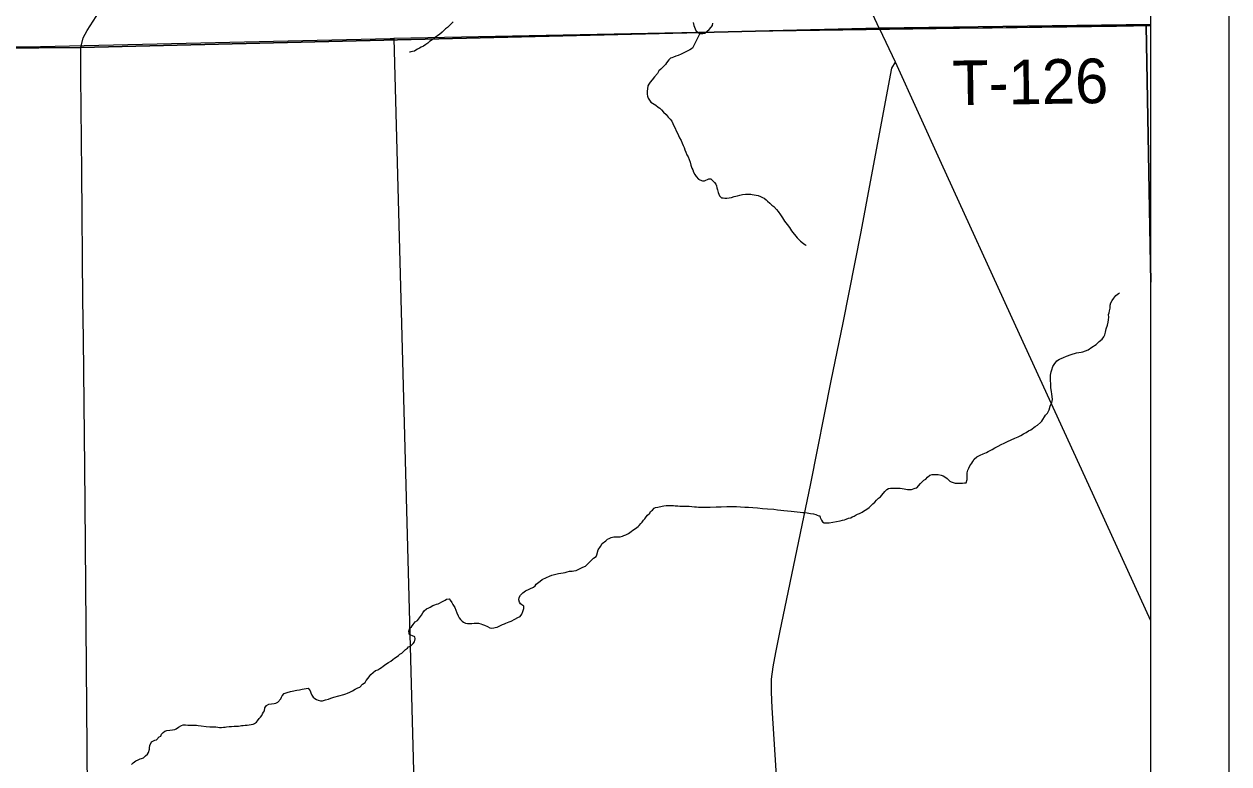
# Model space of a CAD drawing. Extents: x 10.6 to 44.6, y -2.6 to 23.4.
# Drawn here: x 18.57 to 20.103, y 20.016 to 20.958 of the extents above; entities that cross this region are included whole.
import ezdxf

# ---------------------------------------------------------------- set-up
doc = ezdxf.new("R2010")
doc.units = 0
for name, color, linetype in [('GM_X_County', 7, 'Continuous'), ('GM_X_County_Road', 7, 'Continuous'), ('GM_X_Minor_Lake', 7, 'Continuous'), ('GM_X_Minor_River', 7, 'Continuous'), ('GM_X_Section', 7, 'Continuous'), ('GM_X_State_Route', 7, 'Continuous'), ('GM_X_Township', 7, 'Continuous'), ('GM_X_Township_Road', 7, 'Continuous'), ('GM_X_Township_Road_Text', 7, 'Continuous'), ('SH_Data', 7, 'Continuous')]:
    doc.layers.add(name, color=color, linetype=linetype)

msp = doc.modelspace()

# ---------------------------------------------------------------- linework, layer by layer
at = {"layer": 'GM_X_County'}
msp.add_lwpolyline([(20.0033, 15.5302), (20.0033, 22.3267), (13.2033, 22.3267), (13.2033, 15.5267), (19.8413, 15.5267)], dxfattribs=at)
at = {"layer": 'GM_X_County_Road'}
for points in [[(18.6535, 19.6817), (18.6533, 19.7284), (18.6525, 19.7533), (18.6516, 19.8149), (18.6497, 20.0361), (18.6472, 20.3469), (18.6468, 20.3934), (18.645, 20.5569), (18.6444, 20.6072), (18.643, 20.7692), (18.6417, 20.8913), (18.6416, 20.9277), (18.6445, 20.9403), (18.6498, 20.9497), (18.669, 20.9792), (18.7118, 21.0385)], [(19.5512, 19.5913), (19.5484, 19.6433), (19.5465, 19.6819), (19.5455, 19.7043), (19.5377, 19.8318), (19.5279, 19.9874), (19.5216, 20.0873), (19.5206, 20.1073), (19.5206, 20.1237), (19.5228, 20.1393), (19.526, 20.1578), (19.5311, 20.1832), (19.5709, 20.373), (19.5968, 20.5034), (19.6117, 20.5772), (19.6346, 20.6932), (19.6468, 20.7569), (19.6737, 20.9017), (19.6783, 20.9093)]]:
    msp.add_lwpolyline(points, dxfattribs=at)
at = {"layer": 'GM_X_Minor_Lake'}
msp.add_lwpolyline([(19.4209, 20.9599), (19.4217, 20.9561), (19.4228, 20.9538), (19.4244, 20.9496), (19.4274, 20.947), (19.4293, 20.9459), (19.4312, 20.9459), (19.4335, 20.9459), (19.4358, 20.9463), (19.4388, 20.9486), (19.4414, 20.9509), (19.4441, 20.9536), (19.4456, 20.9559), (19.4459, 20.9589)], dxfattribs=at)
at = {"layer": 'GM_X_Minor_River'}
for points in [[(19.1157, 20.9607), (19.1082, 20.9534), (19.1059, 20.9515), (19.1041, 20.9499), (19.1014, 20.9473), (19.098, 20.9446), (19.0961, 20.943), (19.0939, 20.9415), (19.092, 20.94), (19.0901, 20.9384), (19.0875, 20.9369), (19.0856, 20.9354), (19.0833, 20.9334), (19.0807, 20.9319), (19.078, 20.9296), (19.075, 20.9281), (19.0727, 20.9269), (19.0701, 20.9258), (19.0682, 20.9246), (19.0663, 20.9234), (19.064, 20.9227), (19.0618, 20.9223), (19.0606, 20.9219), (19.0602, 20.9219)], [(19.4293, 20.9459), (19.42, 20.9272), (19.4166, 20.9249), (19.4124, 20.9229), (19.409, 20.921), (19.4056, 20.9195), (19.4019, 20.9179), (19.3988, 20.9168), (19.3958, 20.9156), (19.3939, 20.9148), (19.392, 20.9141), (19.3901, 20.9121), (19.3871, 20.9083), (19.3856, 20.9064), (19.3826, 20.903), (19.38, 20.9003), (19.3773, 20.898), (19.3755, 20.8946), (19.3717, 20.8907), (19.3687, 20.8869), (19.3661, 20.8838), (19.3646, 20.8812), (19.3634, 20.8789), (19.3624, 20.8717), (19.3624, 20.8686), (19.3628, 20.866), (19.3639, 20.8633), (19.3655, 20.8607), (19.367, 20.8584), (19.3693, 20.8569), (19.3712, 20.8558), (19.3735, 20.8543), (19.3765, 20.852), (19.3785, 20.8505), (19.3807, 20.8486), (19.3834, 20.8456), (19.3865, 20.8426), (19.3892, 20.8392), (19.3918, 20.8365), (19.3938, 20.8339), (19.3953, 20.8313), (19.3965, 20.8282), (19.398, 20.8252), (19.3995, 20.8218), (19.4011, 20.8188), (19.4023, 20.8157), (19.4038, 20.8127), (19.4057, 20.8093), (19.4069, 20.8063), (19.4084, 20.8032), (19.4096, 20.8006), (19.4104, 20.7975), (19.4115, 20.7945), (19.4131, 20.7911), (19.4146, 20.7885), (19.4158, 20.7854), (19.4173, 20.782), (19.4181, 20.7782), (19.4193, 20.7744), (19.4204, 20.7722), (19.4216, 20.7691), (19.4231, 20.7661), (19.425, 20.7635), (19.4277, 20.7604), (19.4296, 20.7593), (19.4327, 20.7582), (19.4353, 20.7582), (19.441, 20.7605), (19.4433, 20.7609), (19.446, 20.7583), (19.4483, 20.756), (19.4498, 20.7538), (19.4509, 20.7519), (19.4513, 20.7492), (19.4521, 20.7466), (19.4529, 20.7431), (19.4537, 20.7413), (19.4545, 20.739), (19.4571, 20.7367), (19.459, 20.7363), (19.4613, 20.736), (19.464, 20.736), (19.467, 20.7364), (19.4696, 20.7368), (19.4731, 20.738), (19.4753, 20.7387), (19.4776, 20.7391), (19.4803, 20.7399), (19.4837, 20.7407), (19.4878, 20.7411), (19.4916, 20.7411), (19.4943, 20.7412), (19.4962, 20.7408), (19.4985, 20.7404), (19.5011, 20.7401), (19.5038, 20.7393)], [(19.5038, 20.7393), (19.5068, 20.7382), (19.5091, 20.7371), (19.5114, 20.736), (19.5137, 20.7341), (19.5156, 20.7322), (19.5187, 20.7299), (19.5213, 20.7273), (19.5236, 20.7254), (19.5271, 20.7216), (19.529, 20.719), (19.5321, 20.7148), (19.5347, 20.7111), (19.5374, 20.7069), (19.5405, 20.7024), (19.5436, 20.6986), (19.5463, 20.6944), (19.5532, 20.6857), (19.5551, 20.6839), (19.5574, 20.6812), (19.5593, 20.6801), (19.5619, 20.6778), (19.5639, 20.6767), (19.565, 20.676)], [(19.7521, 20.3741), (19.7544, 20.3734), (19.7639, 20.3731), (19.7665, 20.3735), (19.7684, 20.3738), (19.7695, 20.378), (19.7695, 20.3822), (19.7695, 20.3845), (19.7695, 20.3864), (19.7706, 20.3898), (19.7717, 20.3925), (19.7732, 20.3952), (19.7755, 20.3986), (19.777, 20.4009), (19.7788, 20.4039), (19.7822, 20.4066), (19.7864, 20.4089), (19.7902, 20.4105), (19.7924, 20.4113), (19.7943, 20.4124), (19.7966, 20.4136), (19.7989, 20.4147), (19.8015, 20.4163), (19.8049, 20.4182), (19.8091, 20.4205), (19.8129, 20.4224), (19.817, 20.4244), (19.8212, 20.4263), (19.8257, 20.4286), (19.8303, 20.4305), (19.8348, 20.4321), (19.8382, 20.434), (19.8416, 20.4359), (19.845, 20.4379), (19.8476, 20.4398), (19.8507, 20.4413), (19.8563, 20.4455), (19.8594, 20.4471), (19.8631, 20.4505), (19.8646, 20.4524), (19.8695, 20.4597), (19.8718, 20.4624), (19.874, 20.4666), (19.8755, 20.4715), (19.8773, 20.4761), (19.8785, 20.4799), (19.878, 20.4837), (19.8773, 20.4867), (19.8769, 20.4898), (19.8765, 20.492), (19.8761, 20.4951), (19.876, 20.4993), (19.8756, 20.5042), (19.8756, 20.5084), (19.8759, 20.5107), (19.8763, 20.5129), (19.8767, 20.5149), (19.8774, 20.5175), (19.8789, 20.5217), (19.8804, 20.5244), (19.8838, 20.529), (19.8872, 20.5313), (19.8894, 20.532), (19.8925, 20.5332), (19.8963, 20.5348), (19.9019, 20.5371), (19.9087, 20.539), (19.9148, 20.5402), (19.9171, 20.5406), (19.9235, 20.5429), (19.9284, 20.5464), (19.9337, 20.5498), (19.9379, 20.5537), (19.9416, 20.5564), (19.9435, 20.5594), (19.945, 20.5621), (19.9457, 20.5655), (19.9468, 20.5697), (19.9483, 20.5743), (19.9491, 20.5781), (19.9494, 20.5811), (19.9498, 20.5845), (19.9497, 20.588), (19.9505, 20.5902), (19.9508, 20.5925), (19.9516, 20.596), (19.9519, 20.5998), (19.9527, 20.6028), (19.9542, 20.6058), (19.9564, 20.6089), (19.959, 20.6123), (19.9621, 20.6146), (19.9636, 20.6154)], [(19.4096, 20.3439), (19.4127, 20.3439), (19.4161, 20.3439), (19.4195, 20.3436), (19.4226, 20.3432), (19.4252, 20.3432), (19.4279, 20.3429), (19.4305, 20.3429), (19.4336, 20.3429), (19.4377, 20.3426), (19.4427, 20.3426), (19.4503, 20.343), (19.4567, 20.3431), (19.4639, 20.3435), (19.4704, 20.3436), (19.4761, 20.3436), (19.4814, 20.3433), (19.4867, 20.3429), (19.4916, 20.3426), (19.4969, 20.3422), (19.503, 20.3419), (19.5091, 20.3412), (19.5156, 20.3408), (19.5235, 20.3401), (19.5285, 20.3394), (19.5326, 20.3391), (19.5364, 20.3383), (19.541, 20.338), (19.5456, 20.3376), (19.5497, 20.3373), (19.5535, 20.3366), (19.5573, 20.3362), (19.5604, 20.3358), (19.563, 20.3359), (19.5661, 20.3355), (19.5684, 20.3351), (19.5703, 20.3348), (19.5741, 20.3341), (19.5771, 20.3333), (19.579, 20.3326), (19.5809, 20.3318), (19.5824, 20.3315), (19.5828, 20.3296), (19.5844, 20.3261), (19.5855, 20.3239), (19.5878, 20.3228), (19.5901, 20.3228), (19.5939, 20.3228), (19.5988, 20.3236), (19.6033, 20.3244), (19.6079, 20.3252), (19.6109, 20.326), (19.6136, 20.3267), (19.6158, 20.3275), (19.6185, 20.3287), (19.6215, 20.3291), (19.6234, 20.3302), (19.6257, 20.3314), (19.6283, 20.3329), (19.6302, 20.3337), (19.6325, 20.3345), (19.6359, 20.3364), (19.6378, 20.3376), (19.6401, 20.3391), (19.6419, 20.3402), (19.645, 20.3422), (19.6468, 20.3441), (19.6495, 20.3468), (19.6521, 20.3491), (19.6544, 20.3517), (19.657, 20.354), (19.6593, 20.356), (19.6612, 20.3579), (19.6649, 20.3628), (19.6676, 20.3651), (19.6698, 20.3663), (19.6721, 20.3667), (19.6755, 20.3667), (19.6786, 20.3667), (19.6846, 20.3668), (19.6896, 20.3661), (19.6937, 20.3653), (19.6968, 20.365), (19.6987, 20.365), (19.7036, 20.3669), (19.7055, 20.3673), (19.7104, 20.373), (19.7145, 20.3769), (19.7172, 20.3784), (19.7191, 20.3807), (19.7224, 20.3834), (19.7251, 20.3842), (19.7285, 20.3842), (19.7327, 20.3842), (19.7365, 20.3835), (19.7392, 20.3824), (19.7414, 20.3813), (19.7441, 20.379), (19.7476, 20.376), (19.7495, 20.3749), (19.7521, 20.3741)], [(19.1672, 20.189), (19.1691, 20.1894), (19.1717, 20.1901), (19.174, 20.1913), (19.1759, 20.1921), (19.1785, 20.1932), (19.1808, 20.1944), (19.1827, 20.1952), (19.1846, 20.1959), (19.1868, 20.1967), (19.1895, 20.1975), (19.194, 20.2002), (19.1978, 20.2021), (19.2008, 20.2036), (19.2031, 20.2063), (19.2042, 20.2101), (19.2057, 20.2139), (19.2053, 20.2166), (19.203, 20.2185), (19.2011, 20.2196), (19.1999, 20.2219), (19.1992, 20.2249), (19.1995, 20.2276), (19.2014, 20.2306), (19.2044, 20.2337), (19.2078, 20.236), (19.2176, 20.241), (19.2199, 20.2425), (19.2214, 20.2445), (19.2244, 20.2471), (19.2263, 20.2483), (19.2289, 20.2506), (19.2342, 20.2533), (19.238, 20.2548), (19.241, 20.256), (19.2429, 20.2564), (19.2463, 20.2576), (19.2498, 20.2583), (19.2528, 20.2587), (19.2554, 20.2591), (19.2581, 20.2595), (19.2607, 20.2603), (19.2638, 20.2611), (19.2672, 20.2611), (19.2691, 20.2615), (19.2721, 20.2623), (19.2748, 20.2635), (19.2782, 20.265), (19.2808, 20.2662), (19.2838, 20.2677), (19.2865, 20.27), (19.2902, 20.2738), (19.294, 20.2777), (19.2974, 20.28), (19.2982, 20.2819), (19.3, 20.2883), (19.303, 20.2925), (19.3053, 20.2964), (19.3098, 20.2998), (19.312, 20.3021), (19.3139, 20.3029), (19.3166, 20.304), (19.32, 20.3048), (19.3223, 20.3048), (19.3249, 20.3049), (19.328, 20.3049), (19.331, 20.3057), (19.3329, 20.3068), (19.3355, 20.3076), (19.3386, 20.3091), (19.3404, 20.3103), (19.3423, 20.3118), (19.3442, 20.3134), (19.3465, 20.3145), (19.3495, 20.3168), (19.351, 20.318), (19.3521, 20.3195), (19.3544, 20.3218), (19.3559, 20.3237), (19.3578, 20.326), (19.3597, 20.3279), (19.3612, 20.3302), (19.363, 20.3325), (19.3657, 20.3352), (19.3668, 20.3371), (19.3691, 20.339), (19.3713, 20.3413), (19.3732, 20.3421), (19.3759, 20.3429), (19.3816, 20.344), (19.3838, 20.3444), (19.3865, 20.3448), (19.3888, 20.3449), (19.391, 20.3449), (19.3937, 20.3449), (19.396, 20.3449), (19.3979, 20.3445), (19.4017, 20.3446), (19.4039, 20.3442), (19.4062, 20.3442), (19.4096, 20.3439)], [(18.9309, 20.1124), (18.9336, 20.109), (18.9344, 20.1063), (18.9359, 20.1033), (18.9375, 20.101), (18.9394, 20.0991), (18.9417, 20.098), (18.9439, 20.0969), (18.9466, 20.0961), (18.9493, 20.0962), (18.9531, 20.0973), (18.9568, 20.0985), (18.9599, 20.0997), (18.9636, 20.1008), (18.9765, 20.1044), (18.9788, 20.1051), (18.9811, 20.1059), (18.9841, 20.1074), (18.9875, 20.109), (18.9909, 20.1109), (18.9943, 20.1128), (18.9966, 20.1136), (19.0003, 20.1174), (19.0034, 20.1194), (19.0049, 20.122), (19.0075, 20.1251), (19.0097, 20.1278), (19.0109, 20.1297), (19.0139, 20.1324), (19.0169, 20.135), (19.0199, 20.1358), (19.0222, 20.1374), (19.0245, 20.1385), (19.0267, 20.1404), (19.0297, 20.1427), (19.0331, 20.145), (19.0362, 20.1466), (19.0388, 20.1489), (19.0407, 20.1504), (19.043, 20.1516), (19.046, 20.1539), (19.0479, 20.1554), (19.0501, 20.1569), (19.0524, 20.1589), (19.055, 20.1615), (19.0573, 20.1631), (19.0588, 20.165), (19.0611, 20.1658), (19.0648, 20.1692), (19.0663, 20.1711), (19.0671, 20.1753), (19.0667, 20.1776), (19.064, 20.1791), (19.0617, 20.1798), (19.0598, 20.1802), (19.059, 20.1847), (19.0605, 20.1886), (19.0624, 20.1905), (19.0647, 20.1935), (19.0673, 20.1966), (19.0703, 20.1985), (19.0729, 20.202), (19.0752, 20.2054), (19.0771, 20.2084), (19.0786, 20.2107), (19.0816, 20.2134), (19.0846, 20.2146), (19.0865, 20.2153), (19.0899, 20.2177), (19.0922, 20.2184), (19.0944, 20.2192), (19.0963, 20.2196), (19.1028, 20.2231), (19.1054, 20.2242), (19.1073, 20.2254), (19.1103, 20.2262), (19.1119, 20.2243), (19.1138, 20.2212), (19.1153, 20.2186), (19.1176, 20.2148), (19.1188, 20.2114), (19.1203, 20.208), (19.1219, 20.2042), (19.1234, 20.2019), (19.125, 20.1997), (19.1269, 20.1974), (19.1288, 20.1963), (19.1311, 20.1952), (19.1337, 20.1948), (19.1364, 20.1948), (19.1394, 20.1945), (19.1425, 20.1949), (19.1455, 20.1949), (19.1478, 20.1949), (19.1508, 20.1942), (19.1527, 20.1934), (19.1554, 20.1927), (19.1592, 20.1908), (19.1622, 20.1893), (19.1649, 20.1886), (19.1672, 20.189)], [(18.7062, 20.015), (18.7085, 20.0173), (18.7119, 20.02), (18.7145, 20.0211), (18.7172, 20.0223), (18.7191, 20.0227), (18.7213, 20.0238), (18.724, 20.0261), (18.7266, 20.0284), (18.7277, 20.0303), (18.7292, 20.0345), (18.7292, 20.0364), (18.7296, 20.0395), (18.7318, 20.044), (18.736, 20.046), (18.7379, 20.0464), (18.7413, 20.0502), (18.7435, 20.051), (18.7443, 20.0536), (18.7465, 20.0559), (18.7488, 20.0575), (18.7511, 20.0582), (18.7552, 20.059), (18.7583, 20.0591), (18.7613, 20.0595), (18.7632, 20.0606), (18.7662, 20.0625), (18.77, 20.0648), (18.7719, 20.0656), (18.7749, 20.0656), (18.778, 20.0653), (18.781, 20.0653), (18.7836, 20.0653), (18.7863, 20.065), (18.789, 20.065), (18.7912, 20.0646), (18.7947, 20.0643), (18.8011, 20.0635), (18.8057, 20.0632), (18.8087, 20.0632), (18.8114, 20.0629), (18.8136, 20.0629), (18.8159, 20.0625), (18.8182, 20.0622), (18.8209, 20.0622), (18.8235, 20.0626), (18.8254, 20.0626), (18.8273, 20.063), (18.8307, 20.0634), (18.8334, 20.0634), (18.8368, 20.0638), (18.8398, 20.0638), (18.8425, 20.0638), (18.8444, 20.0642), (18.8463, 20.0646), (18.8485, 20.0647), (18.8508, 20.0651), (18.8535, 20.0654), (18.8561, 20.0655), (18.8584, 20.0659), (18.8611, 20.0666), (18.8629, 20.0674), (18.8652, 20.069), (18.8667, 20.0709), (18.8686, 20.0735), (18.8705, 20.0755), (18.872, 20.0774), (18.8731, 20.0797), (18.8742, 20.0816), (18.8754, 20.0835), (18.8761, 20.0873), (18.878, 20.0903), (18.881, 20.0919), (18.8844, 20.0923), (18.8878, 20.0927), (18.8897, 20.0931), (18.8923, 20.0946), (18.8961, 20.0988), (18.8972, 20.1007), (18.898, 20.1026), (18.9006, 20.1053), (18.9044, 20.1069), (18.9086, 20.108), (18.9108, 20.1084), (18.9127, 20.1088), (18.9146, 20.1092), (18.9165, 20.1096), (18.9199, 20.11), (18.9233, 20.1112), (18.926, 20.1116), (18.9283, 20.112), (18.9309, 20.1124)]]:
    msp.add_lwpolyline(points, dxfattribs=at)
at = {"layer": 'GM_X_Section'}
for p, q in [((20.0033, 20.629), (20.0033, 20.9556)), ((20.0033, 19.8622), (20.0033, 20.629))]:
    msp.add_line(p, q, dxfattribs=at)
for points in [[(20.0033, 20.629), (19.9973, 20.9555), (19.4928, 20.9481), (19.0401, 20.9394), (19.0693, 19.8492), (20.0033, 19.8622)], [(20.0033, 20.9556), (19.9973, 20.9555), (20.0033, 20.629)]]:
    msp.add_lwpolyline(points, dxfattribs=at)
msp.add_lwpolyline([(19.0401, 20.9394), (19.0693, 19.8492), (18.1394, 19.8405), (18.1171, 20.9247), (18.1295, 20.9248), (18.5902, 20.929), (19.0353, 20.9393)], close=True, dxfattribs=at)
at = {"layer": 'GM_X_State_Route'}
msp.add_lwpolyline([(20.0033, 20.1982), (19.9244, 20.3708), (19.8318, 20.5733), (19.7372, 20.7804), (19.6783, 20.9093), (19.6586, 20.9511), (19.6579, 20.9527), (19.6256, 21.0225)], dxfattribs=at)
at = {"layer": 'GM_X_Township'}
for p, q in [((20.0033, 20.9573), (20.0033, 20.9581)), ((20.0033, 15.5302), (20.0033, 20.9573))]:
    msp.add_line(p, q, dxfattribs=at)
for points in [[(15.2363, 22.3267), (15.2375, 22.264), (15.2389, 21.9444), (15.2493, 21.2218), (15.2514, 21.0808), (15.2545, 20.8646), (16.6438, 20.8983), (17.623, 20.9197), (18.6416, 20.9277), (19.6581, 20.9527), (20.0033, 20.9573)], [(20.0033, 20.9573), (19.6581, 20.9527), (18.6416, 20.9277), (17.623, 20.9197), (16.6438, 20.8983), (15.2545, 20.8646), (15.2587, 20.5958), (15.2685, 20.051), (15.2709, 19.5646)]]:
    msp.add_lwpolyline(points, dxfattribs=at)
at = {"layer": 'GM_X_Township_Road'}
msp.add_lwpolyline([(19.6586, 20.9511), (19.673, 20.9521), (19.694, 20.9524), (19.8017, 20.9528), (19.9596, 20.9552), (20.0033, 20.9559)], dxfattribs=at)
at = {"layer": 'SH_Data'}
msp.add_line((20.1028, 22.4265), (20.1028, 15.4265), dxfattribs=at)

# ---------------------------------------------------------------- texts
at = {"layer": 'GM_X_Township_Road_Text'}
msp.add_text('T-126', height=0.05682, rotation=0.8421, dxfattribs=at).set_placement((19.7511, 20.8543))

doc.saveas('drawing.dxf')
